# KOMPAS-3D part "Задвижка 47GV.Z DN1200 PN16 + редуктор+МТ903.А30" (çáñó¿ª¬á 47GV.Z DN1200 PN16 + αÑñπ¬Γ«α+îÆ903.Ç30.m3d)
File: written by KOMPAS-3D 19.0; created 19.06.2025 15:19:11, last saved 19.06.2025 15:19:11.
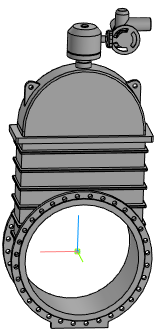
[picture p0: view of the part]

Document properties: Полное имя файла: Задвижка 47GV.Z DN1200 PN16 + редуктор+МТ903.А30.a3d

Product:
- Part/product: Задвижка 47GV.Z DN1200 PN16 + редуктор+МТ903.А30
    Масса: 6743.46

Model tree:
1. Операция без истории:1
